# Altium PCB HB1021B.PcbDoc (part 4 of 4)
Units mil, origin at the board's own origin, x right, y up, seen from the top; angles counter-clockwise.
Board outline 4729.44 x 3075.9 mil, 2 copper layers (Top Layer, Bottom Layer); 113 components, 113 nets, 422 pads, 478 vias.
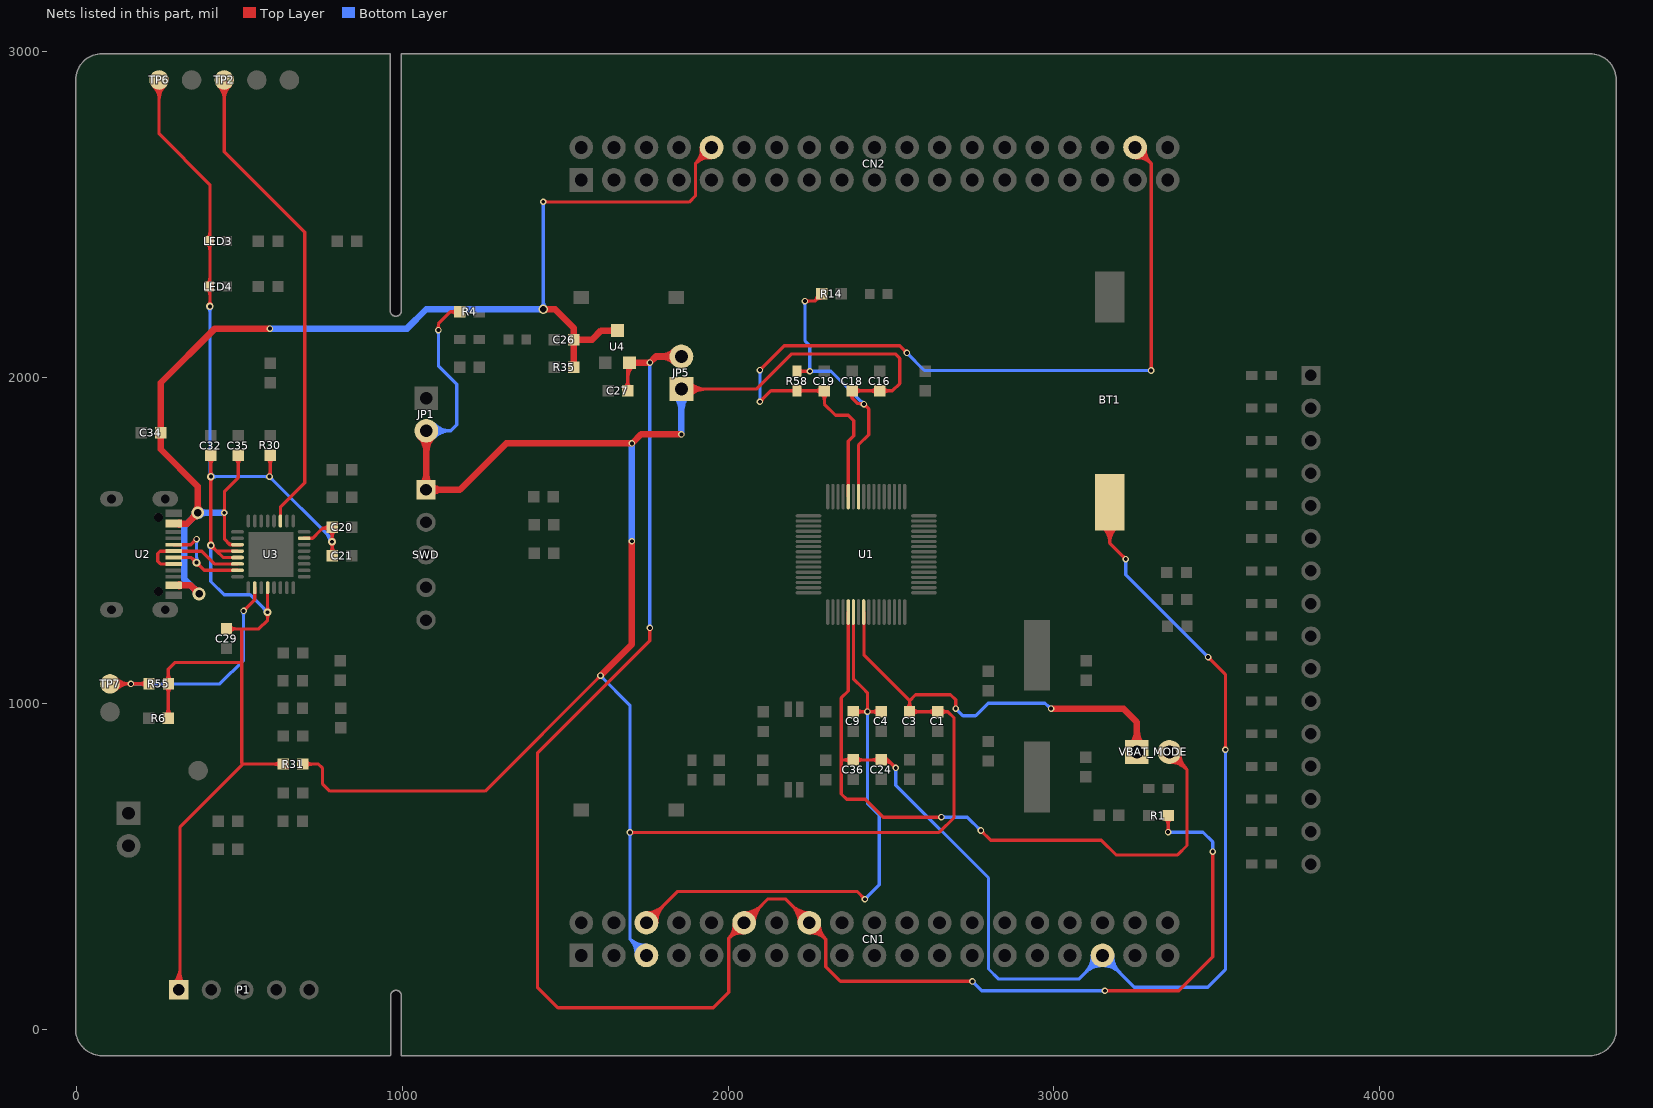
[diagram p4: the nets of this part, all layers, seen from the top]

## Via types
v1: diameter 20, hole 12, Top Layer to Bottom Layer, tented both sides, 451 vias
v2: diameter 23.62, hole 11.81, Top Layer to Bottom Layer, tented both sides, 20 vias
v3: diameter 122.05, hole 122.05, Top Layer to Bottom Layer, tented both sides, 4 vias
v4: diameter 39.37, hole 23.62, Top Layer to Bottom Layer, tented both sides, 2 vias
v5: diameter 30, hole 20, Top Layer to Bottom Layer, tented both sides, 1 vias

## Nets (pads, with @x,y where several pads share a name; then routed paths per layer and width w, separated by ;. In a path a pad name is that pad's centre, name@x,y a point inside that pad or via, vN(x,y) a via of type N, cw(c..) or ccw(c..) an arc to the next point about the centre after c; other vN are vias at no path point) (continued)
PRG_SWDIO: TP2.1 U3.3 | length 1640.5
  Top Layer w10: TP2.1@435.93,2896.11 cw(c393.25,2853.43) 453.61,2853.43 cw(c513.96,2853.43) TP2.1@471.28,2896.11 ; TP2.1@443,2903.18 cw(c417.39,2877.57) 453.61,2877.57 cw(c489.82,2877.57) TP2.1@464.21,2903.18 ; TP2.1@453.61,2913.79 453.61,2693.31 700.61,2446.31 700.61,1677.31 626.13,1602.83 U3.3@626.13,1560.15 U3.3@626.13,1558.18
UPDATE_CTRL: R55.2 TP7.1 U3.18 | length 1026.1
  Top Layer w10: TP7.1@103.35,1060.31 R55.2@222.61,1060.31 ; TP7.1@113.65,1049.39 cw(c140,1023.04) 140,1060.31 ; TP7.1@113.65,1070.61 ccw(c138.51,1095.47) 138.51,1060.31 ; TP7.1@120.72,1042.32 cw(c164.14,998.9) v1@164.14,1060.31 ; TP7.1@120.72,1077.68 ccw(c162.65,1119.61) v1@162.65,1060.31 ; 154.19,1060.31 cw(c154.19,1047.19) v1@163.46,1056.46 ; 155.67,1060.31 ccw(c155.67,1071.33) v1@163.46,1063.54 ; v1@170.54,1056.46 cw(c179.81,1047.19) 179.81,1060.31 ; v1@170.54,1063.54 ccw(c178.33,1071.33) 178.33,1060.31 ; R55.2@213.77,1051.47 ccw(c192.43,1030.13) 192.43,1060.31 ccw(c192.43,1090.49) R55.2@213.77,1069.15 ; v1(513,1284) 547.39,1318.39 U3.18@547.39,1355.43 ; v1@513,1289 ccw(c513,1301.07) 521.54,1292.54 ccw(c530.07,1284) v1@518,1284
  Bottom Layer w10: v1(167,1060) 440,1060 513,1133 v1(513,1284) ; v1@170.54,1056.46 cw(c179.07,1047.93) 179.07,1060 cw(c179.07,1072.07) v1@170.54,1063.54 ; v1@509.46,1280.46 cw(c500.93,1271.93) 513,1271.93 cw(c525.07,1271.93) v1@516.54,1280.46
USB_DM: U2.A7 U2.B7 U3.15 | length 479.4
  Top Layer w10: U2.A7@298.2,1447.87 353.04,1447.87 392.34,1408.57 U3.15@494.24,1408.57 U3.15@496.21,1408.57 ; U2.B7@298.2,1487.24 351.54,1487.24 v1(368.61,1504.31) ; v2@361.93,1432.17 ccw(c345.49,1432.17) 357.12,1443.8 ccw(c368.74,1455.42) v2@368.74,1438.98 ; v1@363.61,1504.31 cw(c351.54,1504.31) 360.07,1495.77 cw(c368.61,1487.24) v1@368.61,1499.31 ; v2@368.74,1425.36 cw(c368.74,1408.92) 380.37,1420.54 cw(c392,1432.17) v2@375.56,1432.17
  Bottom Layer w10: v2@363.93,1436.99 ccw(c352.3,1448.61) 368.74,1448.61 ccw(c385.19,1448.61) v2@373.56,1436.99 ; v1@365.07,1500.77 cw(c356.2,1491.9) 368.74,1491.9 ; v1(368.61,1504.31) 368.74,1504.17 v2(368.74,1432.17) ; 368.74,1492.57 cw(c380.34,1492.57) v1@372.14,1500.77
USB_DP: U2.A6 U2.B6 U3.14 | length 341.8
  Top Layer w10: U2.B6@298.2,1428.18 257.73,1428.18 249.61,1436.31 249.61,1460.31 256.85,1467.55 U2.A6@298.2,1467.55 384.36,1467.55 384.61,1467.31 423.65,1428.26 U3.14@494.24,1428.26 U3.14@496.21,1428.26
VBAT: BT1.1 C24.2 C36.2 CN1.33 U1.5 VBAT_MODE.2 | length 6664.3
  Top Layer w10: 2348.21,826.79 C36.2@2384.6,826.79 C24.2@2470.93,826.79 2490.21,826.79 ; U1.5@2369.15,1280.62 2369.15,1038.15 2348,1017 2348,722 2364,706 2421,706 2476,651 v1(2655,651) ; C36.2@2375.76,817.95 ccw(c2354.42,796.61) 2354.42,826.79 ccw(c2354.42,856.96) C36.2@2375.76,835.62 ; C36.2@2393.44,817.95 cw(c2414.78,796.61) 2414.78,826.79 cw(c2414.78,856.96) C36.2@2393.44,835.62 ; C24.2@2462.1,817.95 ccw(c2440.76,796.61) 2440.76,826.79 ccw(c2440.76,856.96) C24.2@2462.1,835.62 ; C24.2@2470.87,834.29 cw(c2471.11,806.28) 2490.91,826.09 ; C24.2@2470.96,824.29 cw(c2471.41,772.86) 2507.78,809.22 ; C24.2@2472.63,824.94 cw(c2482.33,814.38) 2492.48,824.52 ; C24.2@2479.39,817.58 cw(c2489.4,806.69) 2499.85,817.15 ; C24.2@2482.35,821.69 cw(c2490.21,818.17) 2490.21,826.79 ; C24.2@2482.35,831.89 ccw(c2490.21,835.4) 2490.21,826.79 ; v1@2510,802 ccw(c2497.93,802) 2506.46,810.54 ccw(c2515,819.07) v1@2515,807 ; v1(2515,802) 2490.21,826.79 ; v1@2651.46,647.46 ccw(c2642.93,638.93) 2642.93,651 ccw(c2642.93,663.07) v1@2651.46,654.54 ; v1@2776,605 cw(c2776,592.93) 2784.54,601.46 cw(c2793.07,610) v1@2781,610 ; v1(2776,610) 2806,580 3146,580 3191,535 3380,535 3409,564 3409,797 VBAT_MODE.2@3355,851 ; BT1.1@3146.37,1545.06 cw(c3104.04,1492.4) 3171.61,1492.4 ; BT1.1@3152.64,1552.85 cw(c3120.82,1513.27) 3171.61,1513.27 cw(c3222.4,1513.27) BT1.1@3190.58,1552.85 ; BT1.1@3171.61,1617.79 3171.61,1492.39 ; BT1.1@3196.84,1545.06 ccw(c3239.17,1492.4) 3171.61,1492.4 ; v1@3216,1443 ccw(c3203.93,1443) 3212.46,1451.54 ccw(c3221,1460.07) v1@3221,1448 ; v1(3221,1443) 3171.61,1492.39 ; VBAT_MODE.2@3355,819.58 cw(c3355,743.73) 3408.63,797.37 cw(c3462.27,851) VBAT_MODE.2@3386.42,851 ; VBAT_MODE.2@3355,829.58 cw(c3355,777.88) 3391.56,814.44 cw(c3428.12,851) VBAT_MODE.2@3376.42,851 ; v1@3474,1137 cw(c3474,1124.93) 3482.54,1133.46 cw(c3491.07,1142) v1@3479,1142 ; v1(3474,1142) 3527,1089 v1(3527,858) ; v1@3523.46,861.54 ccw(c3514.93,870.07) 3527,870.07 ccw(c3539.07,870.07) v1@3530.54,861.54
  Bottom Layer w10: v1@2511.46,798.46 cw(c2502.93,789.93) 2515,789.93 cw(c2527.07,789.93) v1@2518.54,798.46 ; v1(2515,802) 2515,749 2799.65,464.35 2799.65,184.87 2830.52,154 3076.82,154 CN1.33@3149.61,226.79 3247.39,129 3473,129 3527,183 v1(3527,858) ; v1(2655,651) 2735,651 v1(2776,610) ; v1@2658.54,647.46 cw(c2667.07,638.93) 2667.07,651 cw(c2667.07,663.07) v1@2658.54,654.54 ; v1@2771,610 ccw(c2758.93,610) 2767.46,618.54 ccw(c2776,627.07) v1@2776,615 ; CN1.33@3118.19,226.79 cw(c3042.34,226.79) 3095.97,173.16 cw(c3149.61,119.52) 3149.61,195.37 cw(c3149.61,119.52) 3203.24,173.16 cw(c3256.87,226.79) CN1.33@3181.02,226.79 ; CN1.33@3128.19,226.79 cw(c3076.48,226.79) 3113.04,190.23 cw(c3149.61,153.67) 3149.61,205.37 cw(c3149.61,153.67) 3186.17,190.23 cw(c3222.73,226.79) CN1.33@3171.02,226.79 ; v1@3217.46,1439.46 cw(c3208.93,1430.93) 3221,1430.93 cw(c3233.07,1430.93) v1@3224.54,1439.46 ; v1(3221,1443) 3221,1395 v1(3474,1142) ; v1@3469,1142 ccw(c3456.93,1142) 3465.46,1150.54 ccw(c3474,1159.07) v1@3474,1147 ; v1@3523.46,854.46 cw(c3514.93,845.93) 3527,845.93 cw(c3539.07,845.93) v1@3530.54,854.46
VBUS_5V: C26.2 C34.2 C35.1 CN2.10 R35.2 U2.A4 U2.A9 U2.B4 U2.B9 U3.11 U4.3 | length 4773.6
  Top Layer w10: v1@450.07,1581.77 cw(c439.12,1570.82) 454.61,1570.82 ; v1@450.07,1588.84 ccw(c439.12,1599.79) 454.61,1599.79 ; 454.61,1538.79 454.61,1518.79 ; 463.85,1494.55 ccw(c480.07,1510.77) U3.11@480.07,1487.83 ; C35.1@487.77,1752.95 cw(c466.43,1731.61) 496.61,1731.61 cw(c526.78,1731.61) C35.1@505.45,1752.95 ; U3.11@496.21,1486.63 U3.11@504.21,1486.63 ; U3.11@496.21,1487.31 U3.11@494.24,1487.31 471.08,1487.31 454.61,1503.79 454.61,1518.79 ; C35.1@496.61,1761.79 496.61,1693.31 454.61,1651.31 454.61,1518.79 ; v1(1433,2540) 1434,2540 1435,2539 1880.48,2539 1900.19,2558.71 1900.19,2657.37 ; v1@1436.54,2543.54 ccw(c1447.49,2554.49) 1447.49,2539 ; CN2.10@1918.24,2704.92 cw(c1856.34,2701.22) 1900.19,2657.37 ; CN2.10@1928.23,2705.51 cw(c1886.03,2703) 1915.92,2673.1 cw(c1945.81,2643.21) CN2.10@1948.33,2685.41 ; CN2.10@1947.74,2675.43 ccw(c1944.04,2613.52) 1900.19,2657.37 ; CN2.10@1949.61,2706.79 1900.19,2657.37
  Top Layer w20: C34.2@253.3,1825.48 cw(c240.5,1812.68) 258.61,1812.68 cw(c276.71,1812.68) C34.2@263.91,1825.48 ; C34.2@253.3,1836.09 ccw(c240.5,1848.89) 258.61,1848.89 ccw(c276.71,1848.89) C34.2@263.91,1836.09 ; U2.B9@286.61,1552.19 340.49,1552.19 372.61,1584.31 v4(372.61,1585.31) 372.61,1666.31 258.61,1780.31 C34.2@258.61,1830.79 258.61,1984.31 425.09,2150.79 v1(593.61,2150.79) ; U2.A9@298.2,1363.21 349.7,1363.21 v4(376.61,1336.31) ; U2.A9@314.99,1360.21 cw(c322.24,1352.95) U2.A9@322.24,1363.21 ; U2.B4@314.99,1366.23 ccw(c322.28,1373.53) U2.A9@322.28,1363.21 ; U2.B9@315,1549.19 cw(c322.26,1541.93) U2.B9@322.26,1552.19 ; U2.A4@315,1555.2 ccw(c322.27,1562.48) U2.B9@322.27,1552.19 ; 355.37,1567.07 ccw(c337.13,1585.31) v4@362.92,1585.31 ; 357.78,1569.48 cw(c372.61,1554.66) v4@372.61,1575.62 ; v4@365.76,1592.16 ccw(c349.22,1608.69) 372.61,1608.69 ccw(c395.99,1608.69) v4@379.45,1592.16 ; v4@366.92,1336.31 ccw(c343.54,1336.31) 360.07,1352.84 ccw(c376.61,1369.37) v4@376.61,1345.99 ; v5(1433,2210) 1469,2210 1527,2152 C26.2@1527,2117 ; R35.2@1521.7,2037.3 ccw(c1508.89,2050.11) 1527,2050.11 ccw(c1545.11,2050.11) R35.2@1532.3,2037.3 ; C26.2@1521.7,2111.7 cw(c1508.89,2098.89) 1527,2098.89 cw(c1545.11,2098.89) 1532.3,2111.7 cw(c1545.11,2098.89) 1545.11,2117 cw(c1545.11,2135.11) 1532.3,2122.3 cw(c1545.11,2135.11) 1527,2135.11 cw(c1508.89,2135.11) C26.2@1521.7,2122.3 ; R35.2@1527,2032 C26.2@1527,2117 ; U4.3@1653.55,2137.58 ccw(c1637.02,2121.04) 1637.02,2144.42 ccw(c1637.02,2167.81) U4.3@1653.55,2151.27 ; U4.3@1660.4,2144.42 1610.42,2144.42 1583,2117 C26.2@1527,2117
  Bottom Layer w10: v5@1425.93,2217.07 ccw(c1408.86,2234.14) 1433,2234.14 ccw(c1457.14,2234.14) v5@1440.07,2217.07 ; v1@1429.46,2536.46 cw(c1420.93,2527.93) 1433,2527.93 cw(c1445.07,2527.93) v1@1436.54,2536.46 ; v5(1433,2210) v1(1433,2540)
  Bottom Layer w20: v4@362.92,1585.31 cw(c339.54,1585.31) 356.07,1568.77 cw(c372.61,1552.24) v4@372.61,1575.62 ; v4@366.92,1336.31 ccw(c343.54,1336.31) 360.07,1352.84 ccw(c376.61,1369.37) v4@376.61,1345.99 ; v4(376.61,1336.31) 331.61,1381.31 331.61,1544.31 v4(372.61,1585.31) v1(453.61,1585.31) ; v4@379.45,1578.46 cw(c395.99,1561.93) 395.99,1585.31 cw(c395.99,1608.69) v4@379.45,1592.16 ; v1(593.61,2150.79) 1014.79,2150.79 1074,2210 v5(1433,2210)
VCORE: C4.1 C9.1 CN1.6 U1.6 | length 2148.1
  Top Layer w10: CN1.6@1749.61,326.79 1845.82,423 2396,423 v1(2420,399) ; CN1.6@1749.61,348.21 ccw(c1749.61,399.91) 1786.17,363.35 ccw(c1822.73,326.79) CN1.6@1771.02,326.79 ; CN1.6@1749.61,358.21 ccw(c1749.61,434.05) 1803.24,380.42 ccw(c1856.87,326.79) CN1.6@1781.02,326.79 ; C9.1@2384.6,974.79 v1(2428,974.79) ; U1.6@2384.9,1280.62 2384.9,1076.1 2414.42,1046.57 2428,1033 v1(2428,974.79) ; C9.1@2393.44,965.95 cw(c2414.78,944.61) 2414.78,974.79 cw(c2414.78,1004.97) C9.1@2393.44,983.63 ; v1@2415,399 ccw(c2402.93,399) 2411.46,407.54 ccw(c2420,416.07) v1@2420,404 ; v1@2424.46,971.25 ccw(c2415.93,962.72) 2415.93,974.79 ccw(c2415.93,986.86) 2424.46,978.32 ccw(c2415.93,986.86) 2428,986.86 ccw(c2440.07,986.86) 2431.54,978.32 ccw(c2440.07,986.86) 2440.07,974.79 ccw(c2440.07,962.72) v1@2431.54,971.25 ; C4.1@2462.1,965.95 ccw(c2440.76,944.61) 2440.76,974.79 ccw(c2440.76,1004.97) C4.1@2462.1,983.63 ; C4.1@2470.93,974.79 v1(2428,974.79)
  Bottom Layer w10: v1(2420,399) 2464,443 2464,656.9 2428,692.9 v1(2428,974.79) ; v1@2420,404 ccw(c2420,416.07) 2428.54,407.54 ccw(c2437.07,399) v1@2425,399 ; v1@2424.46,971.25 cw(c2415.93,962.72) 2428,962.72 cw(c2440.07,962.72) v1@2431.54,971.25
VDD: C1.2 C3.2 C16.1 C18.1 CN1.5 JP1.2 JP5.1 R4.2 R14.2 R31.2 R58.2 SWD.1 U1.8 U1.42 VBAT_MODE.1 | length 10940.1
  Top Layer w10: R31.2@695,814 743,814 755,802 755,754 778,731 1254.21,731 v1(1608.61,1085.39) v1@1611,1083 ; R31.2@703.84,805.16 cw(c725.18,783.82) 725.18,814 cw(c725.18,844.18) R31.2@703.84,822.84 ; v1@1107.46,2149.54 ccw(c1098.93,2158.07) 1111,2158.07 ccw(c1123.07,2158.07) v1@1114.54,2149.54 ; v1(1111,2146) 1111,2165 1148,2202 ; R4.2@1167.91,2193.42 ccw(c1148,2174.61) 1148,2202 ; R4.2@1167.91,2210.58 cw(c1148,2229.39) 1148,2202 ; R4.2@1177,2202 1148,2202 ; v1@1603.61,1085.39 cw(c1591.54,1085.39) 1600.07,1076.86 cw(c1608.61,1068.32) v1@1608.61,1080.39 ; v1(1699,604) 2648,604 2693.79,649.79 2693.79,956.21 2675.21,974.79 C1.2@2643.6,974.79 C3.2@2557.27,974.79 2557.27,1008.73 ; v1@1702.54,600.46 cw(c1711.07,591.93) 1711.07,604 cw(c1711.07,616.07) v1@1702.54,607.54 ; JP5.1@1857,1965 2087,1965 2195,2073 2513,2073 2527,2059 2527,1982 2504.79,1959.79 C16.1@2466,1959.79 C18.1@2381,1959.79 2381,1937 ; JP5.1@1872.14,1949.86 cw(c1908.71,1913.29) 1908.71,1965 cw(c1908.71,2016.71) JP5.1@1872.14,1980.14 ; JP5.1@1879.22,1942.78 cw(c1932.85,1889.15) 1932.85,1965 cw(c1932.85,2040.85) JP5.1@1879.22,1987.22 ; R58.2@2212,2019.79 v1(2251.21,2019.79) ; R58.2@2218.21,2013.58 cw(c2233.2,1998.59) 2233.2,2019.79 cw(c2233.2,2040.98) R58.2@2218.21,2026 ; v1(2236,2235) 2266,2235 R14.2@2288,2257 ; v1@2239.54,2231.46 cw(c2248.07,2222.93) 2248.07,2235 cw(c2248.07,2247.07) v1@2239.54,2238.54 ; v1@2247.68,2016.25 ccw(c2239.14,2007.72) 2239.14,2019.79 ccw(c2239.14,2031.86) v1@2247.68,2023.32 ; R14.2@2275.5,2257 cw(c2245.32,2257) 2266.66,2235.66 cw(c2288,2214.32) R14.2@2288,2244.5 ; C18.1@2374.28,1949.25 cw(c2366.48,1937) 2381,1937 ; C18.1@2387.72,1949.25 ccw(c2395.52,1937) 2381,1937 ; C18.1@2389.84,1950.95 cw(c2411.18,1929.61) 2411.18,1959.79 cw(c2411.18,1989.97) C18.1@2389.84,1968.63 ; 2400.1,1921 cw(c2400.1,1902.1) v1@2413.46,1915.46 ; U1.42@2400.65,1634.95 2400.65,1793.65 2432,1825 2432,1904 v1(2417,1919) 2415,1921 2397,1921 2381,1937 ; U1.8@2416.39,1280.62 2417.14,1279.87 2417.14,1148.86 2557.27,1008.73 ; v1@2417,1914 cw(c2417,1901.93) 2425.54,1910.46 cw(c2434.07,1919) v1@2422,1919 ; C16.1@2457.16,1950.95 ccw(c2435.82,1929.61) 2435.82,1959.79 ccw(c2435.82,1989.97) C16.1@2457.16,1968.63 ; C16.1@2474.84,1950.95 cw(c2496.18,1929.61) 2496.18,1959.79 cw(c2496.18,1989.97) C16.1@2474.84,1968.63 ; C3.2@2548.43,983.63 ccw(c2527.09,1004.96) 2557.27,1004.96 ccw(c2587.45,1004.96) 2566.11,983.63 ccw(c2587.45,1004.96) 2587.45,974.79 ccw(c2587.45,944.61) C3.2@2566.11,965.95 ; C1.2@2634.77,965.95 ccw(c2613.43,944.61) 2613.43,974.79 ccw(c2613.43,1004.96) C1.2@2634.77,983.63 ; C1.2@2652.44,965.95 cw(c2673.78,944.61) 2673.78,974.79 cw(c2673.78,1004.96) C1.2@2652.44,983.63 ; v1@2695.46,987.54 ccw(c2686.93,996.07) 2699,996.07 ccw(c2711.07,996.07) v1@2702.54,987.54 ; v1(2699,984) 2699,1011 2683,1027 2575.54,1027 2557.27,1008.73
  Top Layer w20: JP1.2@1055.32,1818.32 cw(c1010.22,1773.22) 1074,1773.22 cw(c1137.78,1773.22) JP1.2@1092.68,1818.32 ; SWD.1@1059.19,1669.81 ccw(c1023.44,1705.56) 1074,1705.56 ; 1074,1700.73 ccw(c1117.73,1700.73) 1086.81,1669.81 ccw(c1120.14,1703.14) 1120.14,1656 ccw(c1120.14,1608.86) SWD.1@1086.81,1642.19 ; JP1.2@1074,1837 1074,1657 SWD.1@1073,1656 1177,1656 1320,1799 1706,1799 1733,1826 v1(1857,1826) ; v1(1608.61,1085.39) 1705,1181.79 v1(1705,1498) ; v1(2992,984) 3214,984 3255,943 VBAT_MODE.1@3255,851 ; VBAT_MODE.1@3236.32,869.68 ccw(c3191.22,914.78) 3255,914.78 ccw(c3318.78,914.78) VBAT_MODE.1@3273.68,869.68
  Bottom Layer w10: JP1.2@1074,1837 1149,1837 ; JP1.2@1089.26,1821.98 cw(c1125.13,1786.69) 1125.13,1837 cw(c1125.13,1887.31) JP1.2@1089.26,1852.02 ; JP1.2@1096.39,1814.96 cw(c1149,1763.2) 1149,1837 ; JP1.2@1096.39,1859.04 ccw(c1149,1910.8) 1149,1837 ; v1@1107.46,2142.46 cw(c1098.93,2133.93) 1111,2133.93 cw(c1123.07,2133.93) v1@1114.54,2142.46 ; v1(1111,2146) 1111,2036 1167,1980 1167,1855 1149,1837 ; v1@1608.61,1080.39 cw(c1608.61,1068.32) 1617.14,1076.86 cw(c1625.68,1085.39) v1@1613.61,1085.39 ; v1(1608.61,1085.39) 1699.02,994.98 1699.02,277.37 ; v1@1695.46,600.46 cw(c1686.87,591.87) 1699.02,591.87 ; v1@1695.46,607.54 ccw(c1686.87,616.13) 1699.02,616.13 ; 1699.02,591.99 cw(c1711.01,591.99) v1@1702.54,600.46 ; 1699.02,616.01 ccw(c1711.01,616.01) v1@1702.54,607.54 ; CN1.5@1718.22,228.12 ccw(c1652.56,230.9) 1699.03,277.37 ; CN1.5@1728.21,227.69 ccw(c1683.45,229.59) 1715.13,261.27 ccw(c1746.81,292.95) CN1.5@1748.7,248.19 ; CN1.5@1748.28,258.18 cw(c1745.5,323.84) 1699.03,277.37 ; CN1.5@1749.61,226.79 1699.02,277.37 ; v1@2232.46,2231.46 cw(c2223.93,2222.93) 2236,2222.93 cw(c2248.07,2222.93) v1@2239.54,2231.46 ; v1(2236,2235) 2236,2114 2251.21,2098.79 v1(2251.21,2019.79) 2316.21,2019.79 v1(2417,1919) ; v1@2247.68,2023.32 ccw(c2239.14,2031.86) 2251.21,2031.86 ccw(c2263.28,2031.86) 2254.75,2023.32 ccw(c2263.28,2031.86) 2263.28,2019.79 ccw(c2263.28,2007.72) v1@2254.75,2016.25 ; v1@2412,1919 ccw(c2399.93,1919) 2408.46,1927.54 ccw(c2417,1936.07) v1@2417,1924 ; v1@2699,979 cw(c2699,966.93) 2707.54,975.46 cw(c2716.07,984) v1@2704,984 ; v1(2699,984) 2721,962 2760,962 2799,1001 2973,1001 2990,984 v1(2992,984) ; 2980.05,993.95 ccw(c2992,1005.9) v1@2992,989
  Bottom Layer w20: v1(1705,1498) v1(1705,1798) ; JP5.1@1838.32,1946.32 cw(c1793.22,1901.22) 1857,1901.22 cw(c1920.78,1901.22) JP5.1@1875.68,1946.32 ; v1(1857,1826) JP5.1@1857,1965
VDD_LINK: C20.2 C21.2 C29.2 C32.1 LED3.1 LED4.1 P1.1 R6.2 R30.1 R31.1 R55.1 TP6.1 U3.12 U3.13 U3.20 U3.31 | length 6034
  Top Layer w10: TP6.1@235.93,2896.11 cw(c193.25,2853.43) 253.61,2853.43 cw(c313.96,2853.43) TP6.1@271.28,2896.11 ; TP6.1@243,2903.18 cw(c217.39,2877.57) 253.61,2877.57 cw(c289.82,2877.57) TP6.1@264.21,2903.18 ; TP6.1@253.61,2913.79 253.61,2748.31 409.61,2592.31 409.61,2419.31 v2(409.61,2218.79) ; R6.2@273.16,963.84 ccw(c251.82,985.18) 282,985.18 ccw(c312.18,985.18) R6.2@290.84,963.84 ; R55.1@273.77,1051.47 cw(c253.9,1031.6) 282,1031.6 ; R55.1@273.77,1069.15 ccw(c253.9,1089.02) 282,1089.02 ; R6.2@282,955 282,1105 303,1126 507.61,1126 ; 282,1028.66 cw(c314.25,1028.66) R55.1@291.45,1051.47 ; 282,1091.95 ccw(c314.25,1091.95) R55.1@291.45,1069.15 ; P1.1@296.66,138.34 ccw(c245.13,189.87) 318,189.87 ; P1.1@303.73,131.27 ccw(c269.27,165.73) 318,165.73 ; P1.1@318,125 318,621 511,814 ; 318,170.56 ccw(c363.56,170.56) P1.1@331.34,138.34 ; LED4.1@400.54,2272.72 cw(c378.64,2250.82) 409.61,2250.82 ; LED4.1@400.54,2286.86 ccw(c378.64,2308.76) 409.61,2308.76 ; LED3.1@400.54,2412.24 cw(c378.64,2390.34) 409.61,2390.34 ; LED3.1@400.54,2426.38 ccw(c378.64,2448.28) 409.61,2448.28 ; C32.1@403.77,1752.95 cw(c382.43,1731.61) 412.61,1731.61 cw(c442.78,1731.61) C32.1@421.45,1752.95 ; v2@404.79,2223.6 ccw(c393.16,2235.23) 409.61,2235.23 ccw(c426.05,2235.23) v2@414.42,2223.6 ; v2@407.79,1490.12 ccw(c396.16,1501.75) 412.61,1501.75 ccw(c429.05,1501.75) v2@417.42,1490.12 ; v2@407.79,1691.49 cw(c396.16,1679.86) 412.61,1679.86 cw(c429.05,1679.86) v2@417.42,1691.49 ; v2@407.79,1701.12 ccw(c396.16,1712.75) 412.61,1712.75 ccw(c429.05,1712.75) v2@417.42,1701.12 ; 409.61,2260.47 cw(c426.92,2260.47) LED4.1@414.68,2272.72 ; 409.61,2299.1 ccw(c426.92,2299.1) LED4.1@414.68,2286.86 ; 409.61,2399.99 cw(c426.92,2399.99) LED3.1@414.68,2412.24 ; 409.61,2438.62 ccw(c426.92,2438.62) LED3.1@414.68,2426.38 ; v2@412.61,1478.49 cw(c412.61,1462.05) 424.23,1473.68 cw(c435.86,1485.31) v2@419.42,1485.31 ; C32.1@412.61,1761.79 v2(412.61,1696.31) v2(412.61,1485.31) 430.28,1467.63 ; C29.2@460.61,1228.79 507.61,1228.79 ; C29.2@469.45,1219.95 cw(c490.78,1198.61) 490.78,1228.79 cw(c490.78,1258.96) C29.2@469.45,1237.62 ; U3.12@494.24,1467.63 430.28,1467.63 ; U3.13@496.21,1447.94 U3.13@494.24,1447.94 449.97,1447.94 430.28,1467.63 ; v2@581.79,1274.97 cw(c569.78,1262.96) 586.76,1262.96 ; v2@581.79,1284.6 ccw(c569.78,1296.61) 586.76,1296.61 ; R30.1@585.77,1753.47 cw(c564.43,1732.13) 594.61,1732.13 cw(c624.78,1732.13) R30.1@603.45,1753.47 ; 586.76,1263.73 cw(c602.67,1263.73) v2@591.42,1274.97 ; 586.76,1295.85 ccw(c602.67,1295.85) v2@591.42,1284.6 ; U3.20@586.76,1357.39 U3.20@586.76,1355.43 586.76,1255.46 560.09,1228.79 507.61,1228.79 ; v1@589.07,1699.84 ccw(c575.71,1713.2) 594.61,1713.2 ; v1(592.61,1696.31) 594.61,1698.31 R30.1@594.61,1762.31 ; R31.1@626.16,805.16 ccw(c604.82,783.82) 604.82,814 ccw(c604.82,844.18) R31.1@626.16,822.84 ; R31.1@635,814 511,814 ; U3.31@697,1507 U3.31@698.97,1507 724.82,1507 747.61,1529.79 755.61,1537.79 ; 762.67,1537.79 cw(c762.67,1517.85) 776.77,1531.95 cw(c757.84,1513.02) 784.61,1513.02 ; C20.2@775.41,1548.02 cw(c755.61,1562.07) 755.61,1537.79 ; C21.2@776.77,1461.63 ccw(c757.84,1480.55) 784.61,1480.55 ; v2@779.79,1491.49 cw(c768.16,1479.86) 784.61,1479.86 cw(c801.05,1479.86) v2@789.42,1491.49 ; v2@779.79,1501.12 ccw(c768.16,1512.75) 784.61,1512.75 ccw(c801.05,1512.75) v2@789.42,1501.12 ; C21.2@784.61,1447.79 v2(784.61,1496.31) 784.61,1537.79 755.61,1537.79 ; v2@784.61,1485.38 ccw(c818.2,1485.38) C21.2@794.45,1461.63 ; 784.61,1508.2 cw(c818.2,1508.2) C20.2@794.45,1531.95 ; 507.61,1126 507.61,1228.79 ; 507.61,1126 507.61,817.39 511,814
  Bottom Layer w10: v2@404.79,2213.97 cw(c393.16,2202.34) 409.61,2202.34 cw(c426.05,2202.34) v2@414.42,2213.97 ; v2@407.79,1480.49 cw(c396.16,1468.86) 412.61,1468.86 cw(c429.05,1468.86) v2@417.42,1480.49 ; 409.61,1719.99 ccw(c436.29,1719.99) 417.42,1701.12 ccw(c429.05,1712.75) 429.05,1696.31 ccw(c429.05,1679.86) v2@417.42,1691.49 ; v2(409.61,2218.79) 409.61,1699.31 v2(412.61,1696.31) v1(592.61,1696.31) 784.61,1504.31 v2(784.61,1496.31) ; v2(412.61,1485.31) 412.61,1374.31 453.61,1333.31 533.09,1333.31 v2(586.61,1279.79) ; v2@579.8,1279.79 ccw(c563.35,1279.79) 574.98,1291.42 ccw(c586.61,1303.04) v2@586.61,1286.6 ; v1@589.07,1692.77 ccw(c580.54,1684.24) 580.54,1696.31 ccw(c580.54,1708.38) v1@589.07,1699.84 ; v1@592.61,1691.31 cw(c592.61,1679.24) 601.14,1687.77 cw(c609.68,1696.31) v1@597.61,1696.31 ; 767.32,1521.59 cw(c742.04,1496.31) v2@777.8,1496.31
VLCD/PF2: C19.2 CN2.36 R58.1 U1.44 | length 3159.1
  Top Layer w10: v1(2098,1926) 2131.79,1959.79 R58.1@2212,1959.79 C19.2@2296,1959.79 2296,1919 2330,1885 2369,1885 2386,1868 2386,1821.43 2369.15,1804.58 U1.44@2369.15,1634.95 ; v1@2098,1931 ccw(c2098,1943.07) 2106.54,1934.54 ccw(c2115.07,1926) v1@2103,1926 ; v1(2098,2023) 2173,2098 2527,2098 v1(2549,2076) ; v1@2098,2028 ccw(c2098,2040.07) 2106.54,2031.54 ccw(c2115.07,2023) v1@2103,2023 ; R58.1@2205.79,1953.58 ccw(c2190.8,1938.59) 2190.8,1959.79 ccw(c2190.8,1980.98) R58.1@2205.79,1966 ; R58.1@2218.21,1953.58 cw(c2233.2,1938.59) 2233.2,1959.79 cw(c2233.2,1980.98) R58.1@2218.21,1966 ; C19.2@2287.16,1968.63 cw(c2265.82,1989.97) 2265.82,1959.79 cw(c2265.82,1929.61) 2287.16,1950.95 cw(c2265.82,1929.61) 2296,1929.61 cw(c2326.18,1929.61) C19.2@2304.84,1950.95 ; v1@2544,2076 ccw(c2531.93,2076) 2540.46,2084.54 ccw(c2549,2093.07) v1@2549,2081 ; CN2.36@3249.61,2706.79 3299.02,2657.37 ; CN2.36@3250.88,2685.41 cw(c3253.4,2643.21) 3283.29,2673.1 cw(c3313.19,2703) CN2.36@3270.99,2705.51 ; CN2.36@3251.48,2675.43 cw(c3255.17,2613.52) 3299.02,2657.37 ; CN2.36@3280.97,2704.92 ccw(c3342.87,2701.22) 3299.02,2657.37 ; v1@3295.49,2025.54 ccw(c3286.95,2034.08) 3299.02,2034.08 ccw(c3311.1,2034.08) v1@3302.56,2025.54 ; v1(3299.02,2022.01) 3299.02,2657.37
  Bottom Layer w10: v1@2094.46,1929.54 ccw(c2085.93,1938.07) 2098,1938.07 ccw(c2110.07,1938.07) v1@2101.54,1929.54 ; v1@2094.46,2019.46 cw(c2085.93,2010.93) 2098,2010.93 cw(c2110.07,2010.93) v1@2101.54,2019.46 ; v1(2098,1926) v1(2098,2023) ; v1@2549,2071 cw(c2549,2058.93) 2557.54,2067.46 cw(c2566.07,2076) v1@2554,2076 ; v1(2549,2076) 2602.99,2022.01 v1(3299.02,2022.01) ; v1@3295.49,2018.47 ccw(c3286.95,2009.94) 3286.95,2022.01 ccw(c3286.95,2034.08) v1@3295.49,2025.54
VLDO: C27.2 CN1.12 CN1.16 JP5.2 R1.2 U4.2 | length 6680.6
  Top Layer w10: C27.2@1683.16,1968.84 ccw(c1661.82,1990.18) 1692,1990.18 ccw(c1722.18,1990.18) C27.2@1700.84,1968.84 ; U4.2@1687.42,2035.62 cw(c1676.36,2024.56) 1692,2024.56 ; C27.2@1692,1960 1692,2040.2 U4.2@1697.8,2046 ; 1692,1996.54 cw(c1747.27,1996.54) U4.2@1708.19,2035.62 ; 1692,2020.68 cw(c1723.13,2020.68) U4.2@1701.12,2042.69 ; v1@1756.47,1228.46 cw(c1747.93,1219.93) 1760,1219.93 cw(c1772.07,1219.93) v1@1763.54,1228.46 ; v1(1760,1232) 1760,1192 1415,847 1415,129 1478,66 1955,66 2002.19,113.19 2002.19,279.37 ; CN1.12@2018.32,323.94 cw(c1962.7,318.87) 2002.19,279.37 ; CN1.12@2028.28,324.84 cw(c1990.36,321.39) 2017.28,294.46 cw(c2044.21,267.54) CN1.12@2047.66,305.46 ; CN1.12@2046.75,295.5 ccw(c2041.68,239.88) 2002.19,279.37 ; CN1.12@2049.61,348.21 ccw(c2049.61,399.91) 2086.17,363.35 ccw(c2122.73,326.79) CN1.12@2071.02,326.79 ; CN1.12@2049.61,358.21 ccw(c2049.61,434.05) 2103.24,380.42 ccw(c2156.87,326.79) CN1.12@2081.02,326.79 ; CN1.16@2218.19,326.79 ccw(c2142.34,326.79) 2195.97,380.42 ccw(c2249.61,434.05) CN1.16@2249.61,358.21 ; CN1.16@2228.19,326.79 ccw(c2176.48,326.79) 2213.04,363.35 ccw(c2249.61,399.91) CN1.16@2249.61,348.21 ; CN1.16@2250.57,305.39 cw(c2252.57,261.05) 2283.96,292.44 cw(c2315.35,323.82) CN1.16@2271,325.82 ; CN1.16@2251.02,295.4 cw(c2253.95,230.35) 2300,276.4 ; CN1.16@2280.99,325.37 ccw(c2346.04,322.44) 2300,276.4 ; v1@2746.46,143.46 ccw(c2737.93,134.93) 2737.93,147 ccw(c2737.93,159.07) v1@2746.46,150.54 ; v1(2750,147) 2345,147 2300,192 2300,276.39 ; v1(3157,118) 3384,118 3488,222 v1(3488,545) ; v1@3160.54,114.46 cw(c3169.07,105.93) 3169.07,118 cw(c3169.07,130.07) v1@3160.54,121.54 ; R1.2@3342.16,647.16 cw(c3320.82,625.82) 3351,625.82 cw(c3381.18,625.82) R1.2@3359.84,647.16 ; v1@3347.46,608.54 ccw(c3338.93,617.07) 3351,617.07 ccw(c3363.07,617.07) v1@3354.54,608.54 ; v1(3351,605) R1.2@3351,656 ; v1@3484.46,541.46 cw(c3475.93,532.93) 3488,532.93 cw(c3500.07,532.93) v1@3491.54,541.46 ; 2002.19,279.37 2122.82,400 2176.39,400 2300,276.39
  Top Layer w20: U4.2@1697.8,2046 v1(1760,2046) 1779,2065 JP5.2@1857,2065 ; U4.2@1704.65,2039.15 cw(c1721.19,2022.62) 1721.19,2046 cw(c1721.19,2069.38) U4.2@1704.65,2052.85 ; JP5.2@1838.32,2046.32 ccw(c1793.22,2001.22) 1793.22,2065 ccw(c1793.22,2128.78) JP5.2@1838.32,2083.68
  Bottom Layer w10: v1@1756.47,1235.54 ccw(c1747.93,1244.07) 1760,1244.07 ccw(c1772.07,1244.07) v1@1763.54,1235.54 ; v1@1756.47,2042.47 cw(c1747.93,2033.93) 1760,2033.93 cw(c1772.07,2033.93) v1@1763.54,2042.47 ; v1(1760,1232) v1(1760,2046) ; v1@2750,142 cw(c2750,129.93) 2758.54,138.46 cw(c2767.07,147) v1@2755,147 ; v1(2750,147) 2779,118 v1(3157,118) ; v1@3153.46,114.46 ccw(c3144.93,105.93) 3144.93,118 ccw(c3144.93,130.07) v1@3153.46,121.54 ; v1(3351,605) 3458,605 3488,575 v1(3488,545) ; v1@3354.54,601.46 cw(c3363.07,592.93) 3363.07,605 cw(c3363.07,617.07) v1@3354.54,608.54 ; v1@3484.46,548.54 ccw(c3475.93,557.07) 3488,557.07 ccw(c3500.07,557.07) v1@3491.54,548.54
pads on no net: CN1.18 CN1.24 CN2.7 U2. U2.A5 U2.A8 U2.B5 U2.B8 U3.1 U3.4 U3.8 U3.9 U3.10 U3.16 U3.27 U3.28 U3.29 U3.30
copper on no net:
  other v3: 118.11,47.2 4606.3,47.2 118.11,2874.06 4606.3,2874.06

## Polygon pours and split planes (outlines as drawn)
GND on Top Layer "Top Layer-No Net" (solid, remove dead copper, pour order 1000): 82.23,2992.17 33.57,2992.17 7.3,2967 0.06,2960.06 0.06,2913.43 0.06,0.06 0,0 0,-34 24,-57 46.64,-78.69 82.16,-78.69 4661.22,-78.69 4676.15,-78.69 4708.17,-48 4724.41,-32.44 4724.41,-12.45 4724.41,2946.44 4705.04,2965 4676.69,2992.17 4646.61,2992.17
GND on Bottom Layer "Top Layer-No Net" (solid, remove dead copper, pour order 1001): 82.23,2992.13 33.57,2992.13 7.3,2966.95 0.06,2960.01 0.06,2913.39 0.06,0.01 0,-0.05 0,-34.05 24,-57.05 46.64,-78.74 82.16,-78.74 4661.22,-78.74 4676.15,-78.74 4708.17,-48.05 4724.41,-32.49 4724.41,-12.5 4724.41,2946.39 4705.04,2964.95 4676.69,2992.13 4646.61,2992.13

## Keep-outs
Keep-Out Layer:
  lines w5: 0,2913.43 0,0.05 ccw(c78.74,0.05) 78.74,-78.69 962,-78.69 962,103 cw(c981,103) 1000,103 ; 0.06,2913.43 cw(c78.8,2913.43) 78.8,2992.17 959.61,2992.17 ; 960.05,2050.24 cw(c979.52,2043.83) 1000.02,2043.71 ; 960.47,1755.05 ccw(c980.45,1758.4) 999.61,1751.79 ; 960.47,2203.05 ccw(c980.45,2206.4) 999.61,2199.79 ; 960.63,1757.79 960.63,2048.79 ; 960.63,1759.51 960.63,2045.38 ; 960.61,2050.79 cw(c979.76,2044.17) 999.74,2047.53 ; 960.63,2992.17 960.63,2204.83 ccw(c980.31,2204.83) 1000,2204.83 1000,2992.17 4645.67,2992.17 cw(c4645.67,2913.43) 4724.41,2913.43 4724.41,0.05 cw(c4645.67,0.05) 4645.67,-78.69 999.61,-78.69 999.61,103 ; 1000,1754.79 1000,2043.83 ; 1000,1755.79 1000,2042.79 ; 960.63,2045.38 cw(c980.31,2045.38) 1000,2045.38 1000,1756.79 cw(c980.31,1756.79) 960.63,1756.79 960.63,2045.38
  lines w40: 980,217 980,687 ; 980,810 980,1280 ; 980,1392 980,1416 ; 980,1494 980,1671 ; 980,1758 980,2046

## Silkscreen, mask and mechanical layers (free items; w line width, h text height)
Top Overlay:
  lines w5: 1358,1435 1358,1676 1379,1697 1379,1844 ; 1528,176.79 3369,176.79 ; 1528,2556.79 3369,2556.79 ; 1530,376.79 3370,376.79 ; 1530,2756.79 3370,2756.79 ; 1550,904.57 1550,1894 2005.21,1894 2005.21,904.57 1550,904.57
  lines w10: 896,1570 896,1482 896,1413 906,1403 906,1275 ; 1498.91,375.79 1498.91,591.9 ; 1498.91,2339.68 1498.91,2555.79 ; 1498.91,2340.68 3395.6,2340.68 ; 1498.91,2755.79 1498.91,2971.9 ; 1498.91,2972.9 3395.6,2972.9 ; 1499.02,592.9 3395.6,592.9 ; 1501.91,-40.32 1501.91,175.79 ; 1501.91,-39.32 3398.61,-39.32 ; 1598.74,375.79 1598.74,591.9 ; 1598.74,2339.68 1598.74,2555.79 ; 1598.74,2755.79 1598.74,2971.9 ; 1601.74,-40.32 1601.74,175.79 ; 1698.56,375.79 1698.56,591.9 ; 1698.56,2339.68 1698.56,2555.79 ; 1698.56,2755.79 1698.56,2971.9 ; 1701.56,-40.32 1701.56,175.79 ; 1798.39,375.79 1798.39,591.9 ; 1798.39,2339.68 1798.39,2555.79 ; 1798.39,2755.79 1798.39,2971.9 ; 1801.39,-40.32 1801.39,175.79 ; 1898.21,375.79 1898.21,591.9 ; 1898.21,2339.68 1898.21,2555.79 ; 1898.21,2755.79 1898.21,2971.9 ; 1901.22,-40.32 1901.22,175.79 ; 1998.04,375.79 1998.04,591.9 ; 1998.04,2339.68 1998.04,2555.79 ; 1998.04,2755.79 1998.04,2971.9 ; 2001.04,-40.32 2001.04,175.79 ; 2097.87,375.79 2097.87,591.9 ; 2097.87,2339.68 2097.87,2555.79 ; 2097.87,2755.79 2097.87,2971.9 ; 2100.87,-40.32 2100.87,175.79 ; 2197.69,375.79 2197.69,591.9 ; 2197.69,2339.68 2197.69,2555.79 ; 2197.69,2755.79 2197.69,2971.9 ; 2200.69,-40.32 2200.69,175.79 ; 2297.52,375.79 2297.52,591.9 ; 2297.52,2339.68 2297.52,2555.79 ; 2297.52,2755.79 2297.52,2971.9 ; 2300.52,-40.32 2300.52,175.79 ; 2397.34,375.79 2397.34,591.9 ; 2397.34,2339.68 2397.34,2555.79 ; 2397.34,2755.79 2397.34,2971.9 ; 2400.35,-40.32 2400.35,175.79 ; 2497.17,375.79 2497.17,591.9 ; 2497.17,2339.68 2497.17,2555.79 ; 2497.17,2755.79 2497.17,2971.9 ; 2500.17,-40.32 2500.17,175.79 ; 2597,375.79 2597,591.9 ; 2597,2339.68 2597,2555.79 ; 2597,2755.79 2597,2971.9 ; 2600,-40.32 2600,175.79 ; 2696.82,375.79 2696.82,591.9 ; 2696.82,2339.68 2696.82,2555.79 ; 2696.82,2755.79 2696.82,2971.9 ; 2699.82,-40.32 2699.82,175.79 ; 2796.65,375.79 2796.65,591.9 ; 2796.65,2339.68 2796.65,2555.79 ; 2796.65,2755.79 2796.65,2971.9 ; 2799.65,-40.32 2799.65,175.79 ; 2896.47,375.79 2896.47,591.9 ; 2896.47,2339.68 2896.47,2555.79 ; 2896.47,2755.79 2896.47,2971.9 ; 2899.48,-40.32 2899.48,175.79 ; 2996.3,375.79 2996.3,591.9 ; 2996.3,2339.68 2996.3,2555.79 ; 2996.3,2755.79 2996.3,2971.9 ; 2999.3,-40.32 2999.3,175.79 ; 3096.13,375.79 3096.13,591.9 ; 3096.13,2339.68 3096.13,2555.79 ; 3096.13,2755.79 3096.13,2971.9 ; 3099.13,-40.32 3099.13,175.79 ; 3195.95,375.79 3195.95,591.9 ; 3195.95,2339.68 3195.95,2555.79 ; 3195.95,2755.79 3195.95,2971.9 ; 3198.95,-40.32 3198.95,175.79 ; 3295.78,375.79 3295.78,591.9 ; 3295.78,2339.68 3295.78,2555.79 ; 3295.78,2755.79 3295.78,2971.9 ; 3298.78,-40.32 3298.78,175.79 ; 3395.6,375.79 3395.6,591.9 ; 3395.6,2339.68 3395.6,2555.79 ; 3395.6,2755.79 3395.6,2971.9 ; 3398.61,-40.32 3398.61,175.79
  text "PC4" at 2322.61,2950.79 h51.18 r270
  text "PB6" at 2522.61,2950.79 h51.18 r270
  text "PB15" at 2722.61,2950.79 h51.18 r270
  text "PB12" at 2922.61,2950.79 h51.18 r270
  text "PC8" at 1522.61,2949.79 h51.18 r270
  text "PC6" at 1622.61,2949.79 h51.18 r270
  text "PC7" at 1722.61,2949.79 h51.18 r270
  text "GND" at 1822.61,2949.79 h51.18 r270
  text "5V0" at 1921.61,2950.31 h51.18 r270
  text "PC0" at 2022.61,2949.79 h51.18 r270
  text "PC1" at 2122.61,2949.79 h51.18 r270
  text "PC3" at 2222.61,2949.79 h51.18 r270
  text "GND" at 2422.61,2949.79 h51.18 r270
  text "PB2" at 2622.61,2949.79 h51.18 r270
  text "PB13" at 2822.61,2949.79 h51.18 r270
  text "GND" at 3022.61,2949.79 h51.18 r270
  text "PA0" at 3122.61,2949.79 h51.18 r270
  text "VLCD" at 3222.61,2949.79 h51.18 r270
  text "GND" at 3322.61,2949.79 h51.18 r270
  text "CMSIS-DAP" at 38,2709 h51.18 r270
  text "PC9" at 1523.89,2524.55 h51.18 r270
  text "PB8" at 1623.89,2524.55 h51.18 r270
  text "PB9" at 1723.89,2524.55 h51.18 r270
  text "GND" at 1923.89,2525.07 h51.18 r270
  text "PA5" at 2023.89,2524.55 h51.18 r270
  text "PA6" at 2123.89,2524.55 h51.18 r270
  text "PA7" at 2223.89,2524.55 h51.18 r270
  text "PB0" at 2323.89,2524.55 h51.18 r270
  text "PB1" at 2423.89,2524.55 h51.18 r270
  text "PA9" at 2523.89,2524.55 h51.18 r270
  text "PA8" at 2623.89,2525.07 h51.18 r270
  text "PB14" at 2723.89,2524.55 h51.18 r270
  text "PB5" at 2823.89,2524.55 h51.18 r270
  text "PB4" at 2923.89,2524.55 h51.18 r270
  text "PB3" at 3023.89,2524.55 h51.18 r270
  text "PA10" at 3123.89,2524.55 h51.18 r270
  text "PA11" at 3223.89,2525.07 h51.18 r270
  text "PA12" at 3321.89,2524.55 h51.18 r270
  text "NC" at 1823,2498 h51.18 r270
  text "USER" at 1880,2215 h50
  text "PwrTest" at 1921,2156 h50 r270
  text "LITE-64" at 2681,2060 h60 r270
  text "HB1021B" at 2765,2059 h60 r270
  text "BOOT0" at 1135.02,1861 h50
  text "VDD" at 1138,1625 h50
  text "GND" at 1138,1534 h50
  text "SWDIO" at 1134,1430 h50
  text "SWCLK" at 1134,1335 h50
  text "NRST" at 1134,1228 h50
  text "RESET" at 1599.02,748 h50
  text "Vcore" at 1728,569 h51.18 r270
  text "GND" at 2425.61,562.79 h51.18 r270
  text "GND" at 2525.61,562.79 h51.18 r270
  text "PD5" at 2725.61,562.79 h51.18 r270
  text "PA2" at 2925.61,562.79 h51.18 r270
  text "PA3" at 3025.61,562.79 h51.18 r270
  text "PA4" at 3125.61,562.79 h51.18 r270
  text "PB10" at 3225.61,562.79 h51.18 r270
  text "PB11" at 3325.61,562.79 h51.18 r270
  text "VLDO" at 2225.61,562.31 h51.18 r270
  text "PA1" at 2825.61,562.31 h51.18 r270
  text "PD2" at 1525.61,561.33 h51.18 r270
  text "PC11" at 1626.61,561.33 h51.18 r270
  text "PA14" at 1825.61,561.33 h51.18 r270
  text "PA15" at 1925.61,561.33 h51.18 r270
  text "VLDO" at 2025.61,561.31 h51.18 r270
  text "NRST" at 2125.61,561.33 h51.18 r270
  text "NC" at 2321,540 h51.18 r270
  text "NC" at 2623.95,539.05 h51.18 r270
  text "NRST" at 691,352 h50 r270
  text "SCLK" at 587,348 h50 r270
  text "SDIO" at 487,320 h50 r270
  text "VCC" at 290,315 h50 r270
  text "GND" at 389,314 h50 r270
  text "PC12" at 1527.78,137.79 h51.18 r270
  text "VDD" at 1727.78,137.79 h51.18 r270
  text "PA13" at 1827.78,137.79 h51.18 r270
  text "GND" at 1927.78,137.79 h51.18 r270
  text "PD0" at 2127.78,137.79 h51.18 r270
  text "PD3" at 2227.78,137.79 h51.18 r270
  text "PD4" at 2327.78,137.79 h51.18 r270
  text "GND" at 2427.78,137.79 h51.18 r270
  text "PB7" at 2527.78,137.79 h51.18 r270
  text "PC13" at 2627.78,137.79 h51.18 r270
  text "PC15" at 2727.78,137.79 h51.18 r270
  text "PF1" at 2927.78,137.79 h51.18 r270
  text "PF0" at 3027.78,137.79 h51.18 r270
  text "VBAT" at 3127.78,137.79 h51.18 r270
  text "PC5" at 3327.78,137.79 h51.18 r270
  text "PC10" at 1627.78,137.31 h51.18 r270
  text "PD1" at 2027.78,137.31 h51.18 r270
  text "PC14" at 2827.78,137.31 h51.18 r270
  text "PC2" at 3227.78,137.31 h51.18 r270

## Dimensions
0,2913.43 to 4724.41,0.05 on Mechanical 13
999.61,-78.69 to 1000,2992.17 on Mechanical 13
